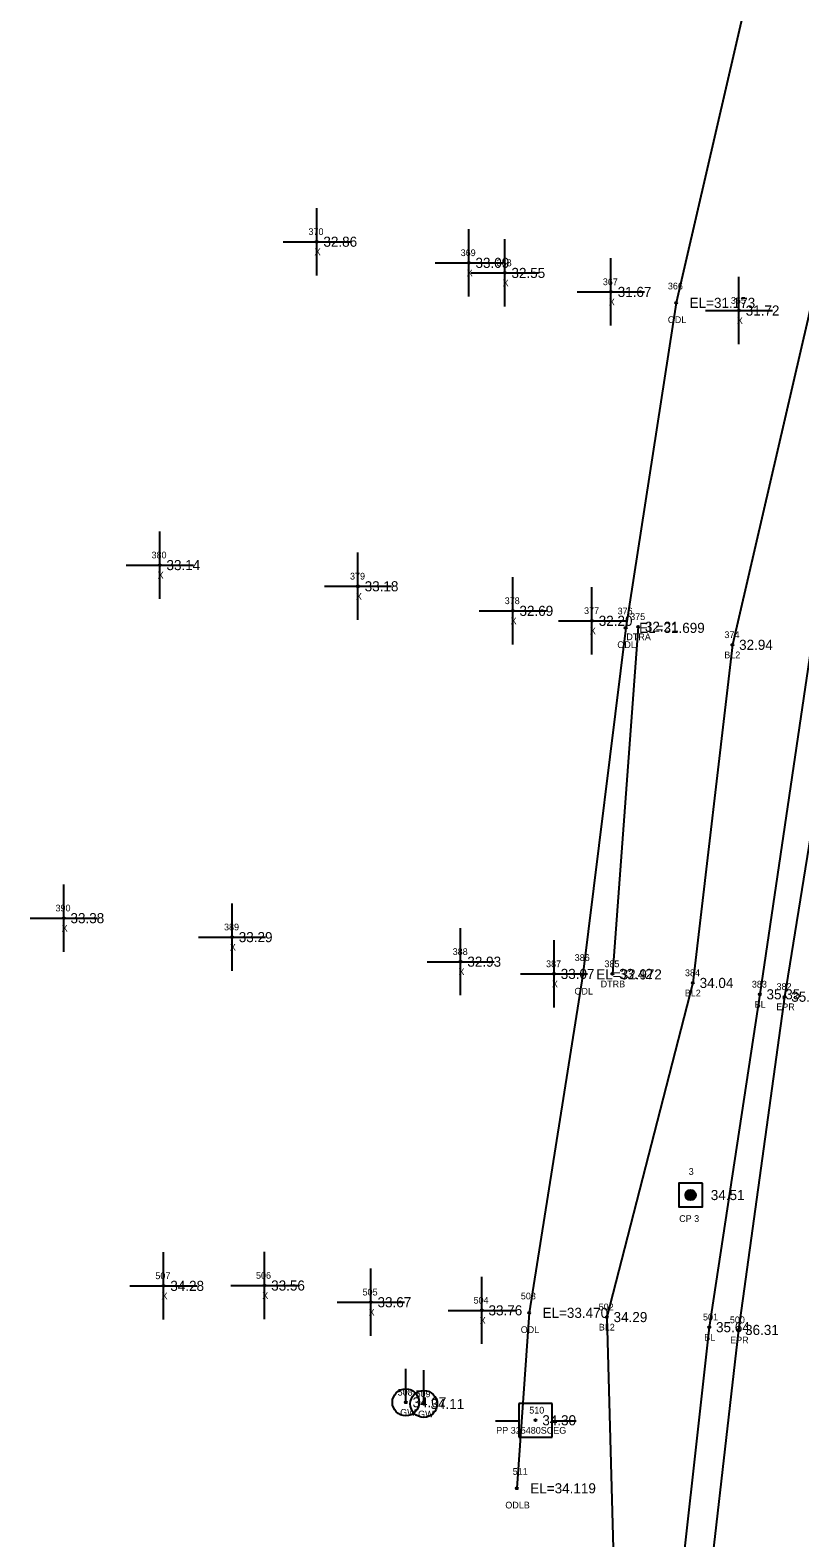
# Model space of a CAD drawing. Extents: x 2042211 to 2045853, y 303080 to 309569.
# Drawn here: x 2042735.4 to 2042849.9, y 307547.4 to 307771.5 of the extents above; entities that cross this region are included whole.
import ezdxf

# ---------------------------------------------------------------- set-up
doc = ezdxf.new("R2010")
doc.units = 0
for name, color, linetype in [('BR_500YR_SCOUR', 7, 'Continuous'), ('RD_DTM_BkLn1', 7, 'Continuous'), ('RD_DTM_BkLn_txCode', 7, 'Continuous'), ('RD_EX_H2O', 7, 'Continuous'), ('RD_EX_H2O_txCode', 7, 'Continuous'), ('RD_EX_Misc', 7, 'Continuous'), ('RD_EX_Misc_txCode', 7, 'Continuous'), ('RD_EX_Road', 7, 'Continuous'), ('RD_EX_Road_txCode', 7, 'Continuous'), ('RD_EX_TX_H2O_ELEV', 7, 'Continuous'), ('RD_EX_TX_Misc_ELEV', 7, 'Continuous'), ('RD_EX_TX_Road_ELEV', 7, 'Continuous'), ('RD_EX_TX_UT_ELEV', 7, 'Continuous'), ('RD_EX_UT_txCode', 7, 'Continuous'), ('RD_HC_Survey_ELEV', 7, 'Continuous'), ('RD_HC_Survey_txCode', 7, 'Continuous'), ('RD_SMD_Locator', 7, 'Continuous')]:
    doc.layers.add(name, color=color, linetype=linetype)

msp = doc.modelspace()

# ---------------------------------------------------------------- linework, layer by layer
at = {"layer": 'BR_500YR_SCOUR'}
for p, q in [((2042832.88, 307598.19), (2042832.88, 307598.55)), ((2042832.91, 307598.11), (2042832.91, 307598.63)), ((2042832.93, 307598.05), (2042832.93, 307598.69)), ((2042832.96, 307598), (2042832.96, 307598.74)), ((2042832.98, 307597.96), (2042832.98, 307598.78)), ((2042833.01, 307597.92), (2042833.01, 307598.82)), ((2042833.03, 307597.89), (2042833.03, 307598.85)), ((2042833.06, 307597.86), (2042833.06, 307598.88)), ((2042833.08, 307597.83), (2042833.08, 307598.91)), ((2042833.11, 307597.81), (2042833.11, 307598.93)), ((2042833.13, 307597.79), (2042833.13, 307598.96)), ((2042833.15, 307597.77), (2042833.15, 307598.98)), ((2042833.18, 307597.75), (2042833.18, 307599)), ((2042833.2, 307597.73), (2042833.2, 307599.01)), ((2042833.23, 307597.72), (2042833.23, 307599.03)), ((2042833.25, 307597.7), (2042833.25, 307599.04)), ((2042833.28, 307597.69), (2042833.28, 307599.06)), ((2042833.3, 307597.68), (2042833.3, 307599.07)), ((2042833.33, 307597.66), (2042833.33, 307599.08)), ((2042833.35, 307597.65), (2042833.35, 307599.09)), ((2042833.38, 307597.65), (2042833.38, 307599.1)), ((2042833.4, 307597.64), (2042833.4, 307599.11)), ((2042833.43, 307597.63), (2042833.43, 307599.11)), ((2042833.45, 307597.62), (2042833.45, 307599.12)), ((2042833.48, 307597.62), (2042833.48, 307599.13)), ((2042833.5, 307597.61), (2042833.5, 307599.13)), ((2042833.53, 307597.61), (2042833.53, 307599.13)), ((2042833.55, 307597.61), (2042833.55, 307599.14)), ((2042833.58, 307597.6), (2042833.58, 307599.14)), ((2042833.6, 307597.6), (2042833.6, 307599.14)), ((2042833.62, 307597.6), (2042833.62, 307599.14)), ((2042833.65, 307597.6), (2042833.65, 307599.14)), ((2042833.67, 307597.6), (2042833.67, 307599.14)), ((2042833.7, 307597.61), (2042833.7, 307599.14)), ((2042833.72, 307597.61), (2042833.72, 307599.14)), ((2042833.75, 307597.61), (2042833.75, 307599.13)), ((2042833.77, 307597.62), (2042833.77, 307599.13)), ((2042833.8, 307597.62), (2042833.8, 307599.12)), ((2042833.82, 307597.63), (2042833.82, 307599.12)), ((2042833.85, 307597.63), (2042833.85, 307599.11)), ((2042833.87, 307597.64), (2042833.87, 307599.1)), ((2042833.9, 307597.65), (2042833.9, 307599.09)), ((2042833.92, 307597.66), (2042833.92, 307599.08)), ((2042833.95, 307597.67), (2042833.95, 307599.07)), ((2042833.97, 307597.68), (2042833.97, 307599.06)), ((2042834, 307597.69), (2042834, 307599.05)), ((2042834.02, 307597.71), (2042834.02, 307599.04)), ((2042834.05, 307597.72), (2042834.05, 307599.02)), ((2042834.07, 307597.74), (2042834.07, 307599)), ((2042834.1, 307597.76), (2042834.1, 307598.99)), ((2042834.12, 307597.78), (2042834.12, 307598.97)), ((2042834.14, 307597.8), (2042834.14, 307598.94)), ((2042834.17, 307597.82), (2042834.17, 307598.92)), ((2042834.19, 307597.85), (2042834.19, 307598.9)), ((2042834.22, 307597.88), (2042834.22, 307598.87)), ((2042834.24, 307597.91), (2042834.24, 307598.84)), ((2042834.27, 307597.94), (2042834.27, 307598.8)), ((2042834.29, 307597.98), (2042834.29, 307598.76)), ((2042834.32, 307598.03), (2042834.32, 307598.72)), ((2042834.34, 307598.08), (2042834.34, 307598.66)), ((2042834.37, 307598.15), (2042834.37, 307598.59)), ((2042834.39, 307598.26), (2042834.39, 307598.48)), ((2042791.27, 307567.56), (2042791.27, 307572.56)), ((2042793.94, 307567.32), (2042793.94, 307572.32)), ((2042813.06, 307567.4), (2042808.06, 307567.4)), ((2042808.06, 307567.4), (2042808.06, 307562.4)), ((2042813.06, 307562.4), (2042813.06, 307567.4)), ((2042804.63, 307564.83), (2042808.1, 307564.83)), ((2042812.99, 307564.83), (2042816.63, 307564.83)), ((2042808.06, 307562.4), (2042813.06, 307562.4))]:
    msp.add_line(p, q, dxfattribs=at)
msp.add_lwpolyline([(2042835.38, 307600.12), (2042831.88, 307600.12), (2042831.88, 307596.62), (2042835.38, 307596.62)], close=True, dxfattribs=at)
for centre, radius in [((2042833.63, 307598.37), 0.769), ((2042833.63, 307598.37), 0.15), ((2042791.27, 307567.56), 2), ((2042793.94, 307567.32), 2), ((2042791.27, 307567.56), 0.15), ((2042793.94, 307567.32), 0.15), ((2042810.57, 307564.89), 0.15)]:
    msp.add_circle(centre, radius, dxfattribs=at)
at = {"layer": 'RD_DTM_BkLn1'}
for points in [[(2042869.74, 307776.07), (2042859.54, 307726.73), (2042851.31, 307678.22), (2042843.92, 307628.21), (2042836.41, 307578.73), (2042830.84, 307528.85), (2042827.5, 307478.96), (2042824.99, 307429.39), (2042821.8, 307378.88), (2042823.15, 307329.29), (2042823.59, 307279.35)], [(2042857.58, 307758.68), (2042851.06, 307728.52), (2042839.84, 307680.16), (2042833.97, 307629.9), (2042821.17, 307580.23), (2042822.56, 307529.56), (2042819.57, 307479.56), (2042814.78, 307429.4), (2042809.83, 307378.82), (2042809.03, 307329.14)]]:
    msp.add_lwpolyline(points, dxfattribs=at)
at = {"layer": 'RD_EX_H2O'}
msp.add_line((2042825.83, 307682.85), (2042821.99, 307631.24), dxfattribs=at)
msp.add_lwpolyline([(2043129.27, 308428.82), (2043103.11, 308386.53), (2043087.59, 308358.52), (2043078.21, 308342.14), (2043052.09, 308299.16), (2043025.98, 308255.36), (2043015.05, 308240.46), (2043007.57, 308236.11), (2042996.98, 308213.48), (2042981.31, 308163.04), (2042956.15, 308118.86), (2042936.41, 308071.81), (2042918.77, 308024.43), (2042903.29, 307975.96), (2042886.4, 307928.42), (2042872.04, 307879.53), (2042857.18, 307831.23), (2042843.33, 307782.22), (2042831.48, 307730.99), (2042823.97, 307682.68), (2042817.59, 307631.17), (2042809.6, 307580.86), (2042807.78, 307554.78)], dxfattribs=at)
at = {"layer": 'RD_EX_Misc'}
for p, q in [((2042778.01, 307735.08), (2042778.01, 307745.08)), ((2042800.63, 307731.94), (2042800.63, 307741.94)), ((2042773.01, 307740.08), (2042783.01, 307740.08)), ((2042805.98, 307730.44), (2042805.98, 307740.44)), ((2042795.63, 307736.94), (2042805.63, 307736.94)), ((2042821.78, 307727.62), (2042821.78, 307737.62)), ((2042800.98, 307735.44), (2042810.98, 307735.44)), ((2042840.82, 307724.85), (2042840.82, 307734.85)), ((2042816.78, 307732.62), (2042826.78, 307732.62)), ((2042835.82, 307729.85), (2042845.82, 307729.85)), ((2042754.67, 307687.01), (2042754.67, 307697.01)), ((2042784.15, 307683.86), (2042784.15, 307693.86)), ((2042749.67, 307692.01), (2042759.67, 307692.01)), ((2042807.17, 307680.21), (2042807.17, 307690.21)), ((2042779.15, 307688.86), (2042789.15, 307688.86)), ((2042818.96, 307678.73), (2042818.96, 307688.73)), ((2042802.17, 307685.21), (2042812.17, 307685.21)), ((2042813.96, 307683.73), (2042823.96, 307683.73)), ((2042740.39, 307634.53), (2042740.39, 307644.53)), ((2042765.42, 307631.71), (2042765.42, 307641.71)), ((2042735.39, 307639.53), (2042745.39, 307639.53)), ((2042799.42, 307628.06), (2042799.42, 307638.06)), ((2042760.42, 307636.71), (2042770.42, 307636.71)), ((2042813.31, 307626.24), (2042813.31, 307636.24)), ((2042794.42, 307633.06), (2042804.42, 307633.06)), ((2042808.31, 307631.24), (2042818.31, 307631.24)), ((2042755.24, 307579.87), (2042755.24, 307589.87)), ((2042770.24, 307579.92), (2042770.24, 307589.92)), ((2042786.06, 307577.44), (2042786.06, 307587.44)), ((2042802.57, 307576.23), (2042802.57, 307586.23)), ((2042750.24, 307584.87), (2042760.24, 307584.87)), ((2042765.24, 307584.92), (2042775.24, 307584.92)), ((2042781.06, 307582.44), (2042791.06, 307582.44)), ((2042797.57, 307581.23), (2042807.57, 307581.23))]:
    msp.add_line(p, q, dxfattribs=at)
at = {"layer": 'RD_EX_Road'}
msp.add_lwpolyline([(2042875.38, 307775.02), (2042864.88, 307726.03), (2042855.57, 307677.22), (2042847.6, 307627.85), (2042840.73, 307578.32), (2042835.07, 307528.58), (2042830.98, 307478.6), (2042828.36, 307428.87), (2042826.99, 307378.91), (2042826.88, 307329.29), (2042828.01, 307279.82)], dxfattribs=at)
at = {"layer": 'RD_SMD_Locator'}
for centre in [(2042778.01, 307740.08), (2042800.63, 307736.94), (2042805.98, 307735.44), (2042821.78, 307732.62), (2042831.48, 307730.99), (2042840.82, 307729.85), (2042754.67, 307692.01), (2042784.15, 307688.86), (2042807.17, 307685.21), (2042818.96, 307683.73), (2042823.97, 307682.68), (2042825.83, 307682.85), (2042839.84, 307680.16), (2042740.39, 307639.53), (2042765.42, 307636.71), (2042799.42, 307633.06), (2042813.31, 307631.24), (2042817.59, 307631.17), (2042821.99, 307631.24), (2042833.97, 307629.9), (2042843.92, 307628.21), (2042847.6, 307627.85), (2042755.24, 307584.87), (2042770.24, 307584.92), (2042786.06, 307582.44), (2042802.57, 307581.23), (2042809.6, 307580.86), (2042821.17, 307580.23), (2042836.41, 307578.73), (2042840.73, 307578.32), (2042807.78, 307554.78)]:
    msp.add_circle(centre, 0.15, dxfattribs=at)

# ---------------------------------------------------------------- texts
at = {"layer": 'RD_DTM_BkLn_txCode'}
for s, p in [('374', (2042838.66, 307681.16)), ('BL2', (2042838.64, 307678.16)), ('384', (2042832.79, 307630.9)), ('BL2', (2042832.76, 307627.9)), ('383', (2042842.74, 307629.21)), ('BL', (2042843.17, 307626.21)), ('502', (2042819.95, 307581.23)), ('BL2', (2042819.97, 307578.23)), ('501', (2042835.47, 307579.73)), ('BL', (2042835.65, 307576.73))]:
    msp.add_text(s, height=1, dxfattribs=at).set_placement(p)
at = {"layer": 'RD_EX_H2O_txCode'}
for s, p in [('366', (2042830.25, 307732.99)), ('ODL', (2042830.24, 307727.99)), ('376', (2042822.77, 307684.68)), ('375', (2042824.64, 307683.85)), ('ODL', (2042822.73, 307679.68)), ('DTRA', (2042824.07, 307680.85)), ('386', (2042816.39, 307633.17)), ('385', (2042820.81, 307632.24)), ('ODL', (2042816.35, 307628.17)), ('DTRB', (2042820.25, 307629.24)), ('503', (2042808.38, 307582.86)), ('ODL', (2042808.36, 307577.86)), ('511', (2042807.17, 307556.78)), ('ODLB', (2042806.07, 307551.78))]:
    msp.add_text(s, height=1, dxfattribs=at).set_placement(p)
at = {"layer": 'RD_EX_Misc_txCode'}
for s, p in [('370', (2042776.79, 307741.08)), ('X', (2042777.7, 307738.08)), ('369', (2042799.43, 307737.94)), ('368', (2042804.78, 307736.44)), ('X', (2042800.32, 307734.94)), ('X', (2042805.67, 307733.44)), ('367', (2042820.57, 307733.62)), ('365', (2042839.62, 307730.85)), ('X', (2042821.46, 307730.62)), ('X', (2042840.51, 307727.85)), ('380', (2042753.45, 307693.01)), ('X', (2042754.35, 307690.01)), ('379', (2042782.97, 307689.86)), ('X', (2042783.84, 307686.86)), ('378', (2042805.98, 307686.21)), ('377', (2042817.78, 307684.73)), ('X', (2042806.85, 307683.21)), ('X', (2042818.64, 307681.73)), ('390', (2042739.17, 307640.53)), ('X', (2042740.08, 307637.53)), ('389', (2042764.23, 307637.71)), ('X', (2042765.1, 307634.71)), ('388', (2042798.24, 307634.06)), ('387', (2042812.13, 307632.24)), ('X', (2042799.1, 307631.06)), ('X', (2042813, 307629.24)), ('507', (2042754.02, 307585.87)), ('506', (2042768.99, 307585.92)), ('X', (2042754.93, 307582.87)), ('X', (2042769.92, 307582.92)), ('505', (2042784.84, 307583.44)), ('504', (2042801.35, 307582.23)), ('X', (2042785.74, 307580.44)), ('X', (2042802.26, 307579.23))]:
    msp.add_text(s, height=1, dxfattribs=at).set_placement(p)
at = {"layer": 'RD_EX_Road_txCode'}
for s, p in [('382', (2042846.41, 307628.85)), ('EPR', (2042846.37, 307625.85)), ('500', (2042839.47, 307579.32)), ('EPR', (2042839.51, 307576.32))]:
    msp.add_text(s, height=1, dxfattribs=at).set_placement(p)
at = {"layer": 'RD_EX_TX_H2O_ELEV'}
for s, p in [('EL=31.173', (2042833.48, 307730.24)), ('EL=31.699', (2042825.97, 307681.93)), ('32.21', (2042826.83, 307682.1)), ('EL=32.972', (2042819.59, 307630.42)), ('33.42', (2042822.99, 307630.49)), ('EL=33.470', (2042811.6, 307580.11)), ('EL=34.119', (2042809.78, 307554.03))]:
    msp.add_text(s, height=1.5, dxfattribs=at).set_placement(p)
at = {"layer": 'RD_EX_TX_Misc_ELEV'}
for s, p in [('32.86', (2042779.01, 307739.33)), ('33.09', (2042801.63, 307736.19)), ('32.55', (2042806.98, 307734.69)), ('31.67', (2042822.78, 307731.87)), ('31.72', (2042841.82, 307729.1)), ('33.14', (2042755.67, 307691.26)), ('33.18', (2042785.15, 307688.11)), ('32.69', (2042808.17, 307684.46)), ('32.20', (2042819.96, 307682.98)), ('32.94', (2042840.84, 307679.41)), ('33.38', (2042741.39, 307638.78)), ('33.29', (2042766.42, 307635.96)), ('32.93', (2042800.42, 307632.31)), ('33.07', (2042814.31, 307630.49)), ('34.04', (2042834.97, 307629.15)), ('35.35', (2042844.92, 307627.46)), ('34.28', (2042756.24, 307584.12)), ('33.56', (2042771.24, 307584.17)), ('33.67', (2042787.06, 307581.69)), ('33.76', (2042803.57, 307580.48)), ('34.29', (2042822.17, 307579.48)), ('35.64', (2042837.41, 307577.98))]:
    msp.add_text(s, height=1.5, dxfattribs=at).set_placement(p)
at = {"layer": 'RD_EX_TX_Road_ELEV'}
for s, p in [('35.98', (2042848.6, 307627.1)), ('36.31', (2042841.73, 307577.57))]:
    msp.add_text(s, height=1.5, dxfattribs=at).set_placement(p)
at = {"layer": 'RD_EX_TX_UT_ELEV'}
for s, p in [('34.07', (2042792.27, 307566.81)), ('34.11', (2042794.94, 307566.57))]:
    msp.add_text(s, height=1.5, dxfattribs=at).set_placement(p)
at = {"layer": 'RD_EX_UT_txCode'}
for s, p in [('508', (2042790.05, 307568.56)), ('509', (2042792.72, 307568.32)), ('GW', (2042790.43, 307565.56)), ('GW', (2042793.1, 307565.32)), ('510', (2042809.63, 307565.89)), ('PP 325480SCEG', (2042804.72, 307562.89))]:
    msp.add_text(s, height=1, dxfattribs=at).set_placement(p)
at = {"layer": 'RD_HC_Survey_ELEV'}
for s, p in [('34.51', (2042836.63, 307597.62)), ('34.30', (2042811.57, 307564.14))]:
    msp.add_text(s, height=1.5, dxfattribs=at).set_placement(p)
at = {"layer": 'RD_HC_Survey_txCode'}
for s, p in [('3', (2042833.35, 307601.37)), ('CP 3', (2042831.93, 307594.37))]:
    msp.add_text(s, height=1, dxfattribs=at).set_placement(p)

doc.saveas('drawing.dxf')
